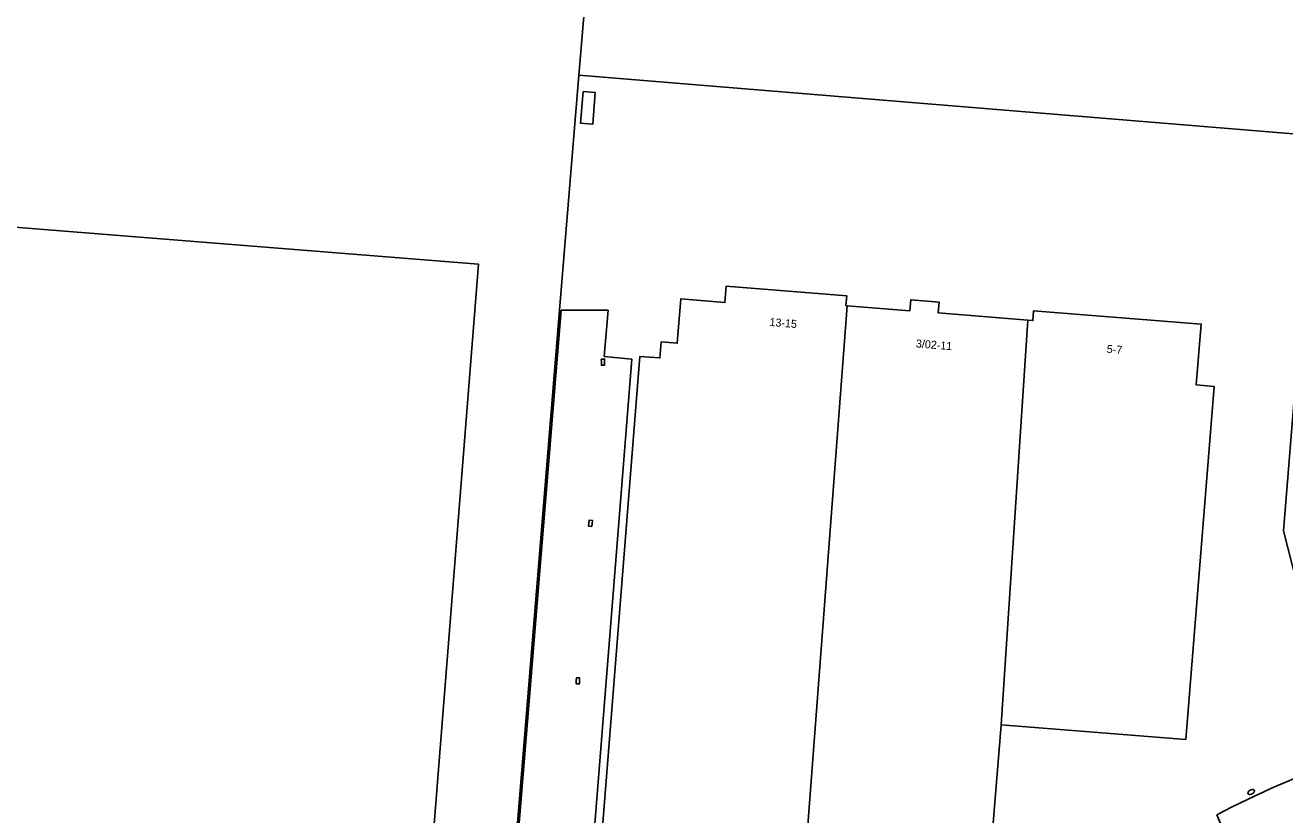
# Model space of a CAD drawing. Extents: x 131000 to 133013, y 393000 to 396501.
# Drawn here: x 131146.8 to 131304.2, y 394437 to 394535.6 of the extents above; entities that cross this region are included whole.
import ezdxf

# ---------------------------------------------------------------- set-up
doc = ezdxf.new("R2010")
doc.units = 0
for name, color, linetype in [('gg-afsc-hekwerk', 7, 'Continuous'), ('gg-anno-huisnummerreeks BGT', 7, 'Continuous'), ('gg-bbg-bijgebouw', 7, 'Continuous'), ('gg-bbg-hoofdgebouw', 7, 'Continuous'), ('gg-bbg-luifel en loopbrug', 7, 'Continuous'), ('gg-bbg-tussenscheiding', 7, 'Continuous'), ('gg-knt-verharding', 7, 'Continuous'), ('gt-grn-vlakafsluiter', 7, 'Continuous'), ('gt-symb-brandkraan', 7, 'Continuous'), ('gt-symb-kolk', 7, 'Continuous')]:
    doc.layers.add(name, color=color, linetype=linetype)

# ---------------------------------------------------------------- blocks, each defined once
blk = doc.blocks.new('gt0-BR')
at = {"layer": 'gt-symb-brandkraan'}
for centre, radius, start, end in [((-0.24, 0), 0.206, 107.5669, 252.4331), ((0.6, -2.66), 3, 106.892, 107.5669), ((0, -0.69), 0.938, 73.108, 106.892), ((-0.6, -2.66), 3, 72.4331, 73.108), ((0.24, 0), 0.206, 287.567, 72.4331), ((0.6, 2.66), 3, 252.4331, 253.108), ((0, 0.69), 0.938, 253.108, 286.8921), ((-0.6, 2.66), 3, 286.8921, 287.567)]:
    blk.add_arc(centre, radius, start, end, dxfattribs=at)
blk = doc.blocks.new('gt0-KOLK')
at = {"layer": 'gt-symb-kolk'}
blk.add_lwpolyline([(0, 0), (0.37, 0), (0.37, 0.4), (-0.38, 0.4), (-0.38, 0), (0, 0)], dxfattribs=at)

msp = doc.modelspace()

# ---------------------------------------------------------------- linework, layer by layer
at = {"layer": 'gg-afsc-hekwerk'}
for p, q in [((131216.73, 394538.71), (131215.96, 394529.38)), ((131213.54, 394500), (131215.96, 394529.38)), ((131204.73, 394392.85), (131213.54, 394500))]:
    msp.add_line(p, q, dxfattribs=at)
for points in [[(131307.97, 394521.8), (131307.16, 394511.56), (131307.7, 394511.51), (131306.84, 394506.19), (131306.54, 394503.86), (131303.98, 394472.43), (131308.93, 394453.02), (131309.61, 394453.16)], [(131295.68, 394436.98), (131296.47, 394435.09), (131272.24, 394419.9)]]:
    msp.add_lwpolyline(points, dxfattribs=at)
msp.add_arc((131351.06, 394331.56), 119.08, 109.4952, 117.7132, dxfattribs=at)
at = {"layer": 'gg-bbg-bijgebouw'}
msp.add_lwpolyline([(131130.13, 394483.29), (131132.37, 394511.42), (131203.44, 394505.74), (131196.29, 394415.81)], dxfattribs=at)
at = {"layer": 'gg-bbg-hoofdgebouw'}
msp.add_line((131291.81, 394446.39), (131268.72, 394448.22), dxfattribs=at)
for points in [[(131243.08, 394417.11), (131217.61, 394419.14), (131223.59, 394494.24), (131226.08, 394494.04), (131226.24, 394496.05), (131228.24, 394495.89), (131228.68, 394501.41), (131234.2, 394500.97), (131234.36, 394502.99), (131249.42, 394501.79), (131249.32, 394500.58), (131249.47, 394500.57)], [(131249.47, 394500.57), (131257.31, 394499.94), (131257.42, 394501.31), (131260.97, 394501.02), (131260.86, 394499.66), (131272.04, 394498.77)], [(131272.04, 394498.77), (131272.68, 394498.72), (131272.77, 394499.93), (131293.71, 394498.27), (131293.1, 394490.67), (131295.32, 394490.49), (131291.81, 394446.39)], [(131268.72, 394448.22), (131267.57, 394433.87), (131250.32, 394435.24)]]:
    msp.add_lwpolyline(points, dxfattribs=at)
at = {"layer": 'gg-bbg-luifel en loopbrug'}
msp.add_lwpolyline([(131216.51, 394527.32), (131216.18, 394523.36), (131217.69, 394523.24), (131218.01, 394527.2), (131216.51, 394527.32)], dxfattribs=at)
at = {"layer": 'gg-bbg-tussenscheiding'}
for p, q in [((131244.57, 394435.7), (131249.47, 394500.57)), ((131272.04, 394498.77), (131268.72, 394448.22))]:
    msp.add_line(p, q, dxfattribs=at)
at = {"layer": 'gg-knt-verharding'}
msp.add_line((131213.74, 394500), (131207.04, 394418.04), dxfattribs=at)
msp.add_lwpolyline([(131219.61, 394500), (131219.14, 394494.24), (131222.59, 394493.88), (131217.29, 394427.49), (131213.84, 394427.78)], dxfattribs=at)
at = {"layer": 'gt-grn-vlakafsluiter'}
for p, q in [((131215.96, 394529.38), (131307.97, 394521.8)), ((131213.74, 394500), (131219.61, 394500))]:
    msp.add_line(p, q, dxfattribs=at)

# ---------------------------------------------------------------- block references
at = {"layer": 'gt-symb-brandkraan', "rotation": -150.84518962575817}
msp.add_blockref('gt0-BR', (131299.95, 394439.82), dxfattribs=at)
at = {"layer": 'gt-symb-kolk'}
for p, rotation in [((131218.77, 394493.51), -89.02606556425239), ((131217.21, 394473.4), -95.10624172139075), ((131215.64, 394453.7), -91.83467292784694)]:
    msp.add_blockref('gt0-KOLK', p, dxfattribs=dict(at, rotation=rotation))

# ---------------------------------------------------------------- texts
at = {"layer": 'gg-anno-huisnummerreeks BGT'}
for s, rotation, p in [('13-15', 355.4, (131239.75, 394498.05)), ('3/02-11', 355.4, (131258.04, 394495.37)), ('5-7', 355.5, (131281.88, 394494.69))]:
    msp.add_text(s, height=1, rotation=rotation, dxfattribs=at).set_placement(p)

doc.saveas('drawing.dxf')
